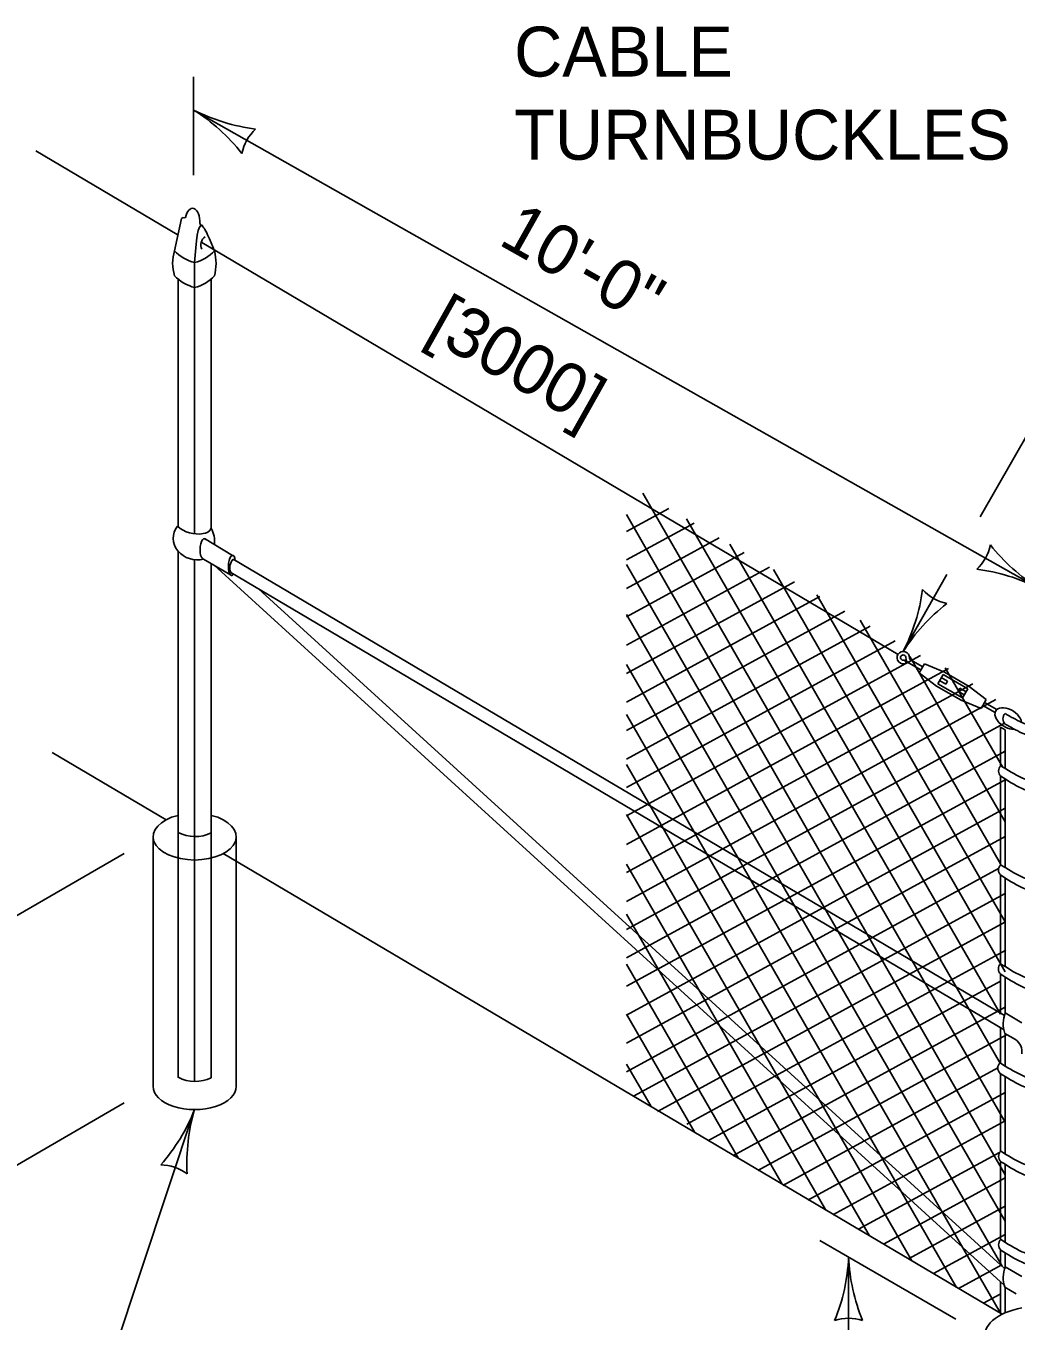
# Model space of a CAD drawing. Extents: x 49973.1 to 50021, y 49987.6 to 50015.4.
# Drawn here: x 50000.641 to 50001.832, y 49994.622 to 49996.179 of the extents above; entities that cross this region are included whole.
import ezdxf

# ---------------------------------------------------------------- set-up
doc = ezdxf.new("R2010")
doc.units = 0
for name, color, linetype in [('Level 1', 7, 'Continuous'), ('Level 2', 7, 'Continuous'), ('Level 3', 7, 'Continuous'), ('Level 4', 7, 'Continuous')]:
    doc.layers.add(name, color=color, linetype=linetype)

msp = doc.modelspace()

# ---------------------------------------------------------------- linework, layer by layer
at = {"layer": 'Level 1'}
for p, q in [((50000.823, 49995.9282), (50000.653, 49996.0287)), ((50000.8199, 49995.9087), (50000.8283, 49995.9476)), ((50000.8619, 49995.9231), (50000.868, 49995.9085)), ((50001.69, 49995.4236), (50000.8529, 49995.9185)), ((50000.8441, 49995.5685), (50000.8441, 49995.8944)), ((50000.8241, 49995.5771), (50000.8241, 49995.8748)), ((50000.8641, 49995.5748), (50000.8641, 49995.8748)), ((50001.8189, 49994.8612), (50001.3832, 49995.6173)), ((50001.3636, 49995.5713), (50001.4144, 49995.599)), ((50001.8189, 49994.7979), (50001.3636, 49995.5915)), ((50001.3636, 49995.5371), (50001.4447, 49995.5813)), ((50001.8133, 49994.9312), (50001.4357, 49995.5866)), ((50000.8898, 49995.5426), (50000.8558, 49995.5627)), ((50001.3636, 49995.5029), (50001.4749, 49995.5637)), ((50000.8241, 49995.2094), (50000.8241, 49995.5476)), ((50001.3636, 49995.4688), (50001.5051, 49995.546)), ((50001.8133, 49994.9911), (50001.4878, 49995.5561)), ((50000.8441, 49995.2044), (50000.8441, 49995.5373)), ((50000.8872, 49995.519), (50000.8548, 49995.5381)), ((50000.8641, 49995.209), (50000.8641, 49995.5326)), ((50000.8674, 49995.5307), (50001.8178, 49994.6655)), ((50001.8179, 49994.9895), (50000.8903, 49995.5378)), ((50001.8189, 49994.7421), (50001.3636, 49995.5315)), ((50001.8177, 49994.9722), (50000.8875, 49995.522)), ((50001.3636, 49995.4346), (50001.5354, 49995.5283)), ((50001.8189, 49995.042), (50001.5401, 49995.5256)), ((50000.9208, 49995.5023), (50001.8182, 49994.6855)), ((50001.3636, 49995.4006), (50001.5656, 49995.5107)), ((50001.3636, 49995.3662), (50001.5958, 49995.493)), ((50001.8189, 49995.1021), (50001.5924, 49995.495)), ((50001.3636, 49995.332), (50001.6261, 49995.4753)), ((50001.8154, 49994.688), (50001.3636, 49995.4713)), ((50001.3636, 49995.2975), (50001.6564, 49995.4576)), ((50001.8133, 49995.1718), (50001.6446, 49995.4645)), ((50001.3636, 49995.2635), (50001.6866, 49995.44)), ((50001.3636, 49995.2293), (50001.7169, 49995.4223)), ((50001.8131, 49994.6317), (50001.3636, 49995.4115)), ((50001.3636, 49995.1951), (50001.7507, 49995.4066)), ((50001.6979, 49995.4168), (50001.7, 49995.4131)), ((50001.7027, 49995.4134), (50001.7176, 49995.4049)), ((50001.8189, 49995.2222), (50001.7043, 49995.4209)), ((50001.7049, 49995.4171), (50001.7197, 49995.4086)), ((50001.7155, 49995.4012), (50001.7219, 49995.4123)), ((50001.7458, 49995.4022), (50001.7219, 49995.4123)), ((50001.8156, 49995.2883), (50001.7467, 49995.4074)), ((50001.7155, 49995.4012), (50001.7362, 49995.3855)), ((50001.7378, 49995.3883), (50001.7442, 49995.3995)), ((50001.7399, 49995.392), (50001.7473, 49995.3878)), ((50001.742, 49995.3957), (50001.7495, 49995.3915)), ((50001.7739, 49995.3823), (50001.7442, 49995.3995)), ((50001.7755, 49995.3851), (50001.7458, 49995.4022)), ((50001.7473, 49995.3878), (50001.7495, 49995.3915)), ((50001.3636, 49995.1612), (50001.78, 49995.3883)), ((50001.7659, 49995.3684), (50001.7362, 49995.3855)), ((50001.7675, 49995.3712), (50001.7378, 49995.3883)), ((50001.7622, 49995.3792), (50001.7643, 49995.3829)), ((50001.7696, 49995.3749), (50001.7622, 49995.3792)), ((50001.7718, 49995.3786), (50001.7643, 49995.3829)), ((50001.7675, 49995.3712), (50001.7739, 49995.3823)), ((50001.7962, 49995.3695), (50001.7755, 49995.3851)), ((50001.3636, 49995.1267), (50001.8076, 49995.3694)), ((50001.7659, 49995.3684), (50001.7898, 49995.3584)), ((50001.7898, 49995.3584), (50001.7962, 49995.3695)), ((50001.8067, 49995.3536), (50001.7919, 49995.3621)), ((50001.8088, 49995.3573), (50001.794, 49995.3658)), ((50001.7605, 49994.6627), (50001.3636, 49995.3513)), ((50001.3636, 49995.0928), (50001.818, 49995.3409)), ((50001.8133, 49995.2894), (50001.8133, 49995.3361)), ((50001.8133, 49995.3361), (50001.8189, 49995.3328)), ((50001.8189, 49995.286), (50001.8189, 49995.3328)), ((50000.8097, 49995.2248), (50000.6726, 49995.3058)), ((50001.3636, 49995.0589), (50001.8189, 49995.3071)), ((50001.7065, 49994.6947), (50001.3636, 49995.2911)), ((50001.3636, 49995.0247), (50001.8189, 49995.2729)), ((50001.8133, 49995.1703), (50001.8133, 49995.2775)), ((50001.8189, 49995.1668), (50001.8189, 49995.2735)), ((50001.3636, 49994.9899), (50001.8189, 49995.2388)), ((50001.6558, 49994.7246), (50001.3636, 49995.2312)), ((50000.7941, 49994.9044), (50000.7941, 49995.2044)), ((50000.8941, 49994.9044), (50000.8941, 49995.2044)), ((50001.3636, 49994.9562), (50001.8189, 49995.2047)), ((50001.8152, 49994.6304), (50000.8785, 49995.1841)), ((50001.6032, 49994.7557), (50001.3636, 49995.1712)), ((50001.3636, 49994.9219), (50001.811, 49995.166)), ((50001.8133, 49995.0514), (50001.8133, 49995.1584)), ((50001.8189, 49995.0479), (50001.8189, 49995.1542)), ((50001.372, 49994.8925), (50001.8189, 49995.1363)), ((50001.5508, 49994.7867), (50001.3636, 49995.1113)), ((50001.4009, 49994.874), (50001.8191, 49995.1022)), ((50001.4359, 49994.8589), (50001.8195, 49995.0682)), ((50001.4981, 49994.8178), (50001.3636, 49995.0512)), ((50001.8133, 49994.9921), (50001.8133, 49995.0394)), ((50001.8189, 49994.992), (50001.8189, 49995.0353)), ((50001.4614, 49994.8387), (50001.8133, 49995.0307)), ((50001.4456, 49994.8489), (50001.3636, 49994.9912)), ((50001.4914, 49994.8209), (50001.8182, 49994.9993)), ((50001.8189, 49994.9926), (50001.8391, 49994.9808)), ((50001.8133, 49994.9318), (50001.8133, 49994.975)), ((50001.5215, 49994.803), (50001.8203, 49994.9661)), ((50001.8186, 49994.968), (50001.8312, 49994.9606)), ((50001.8189, 49994.9282), (50001.8189, 49994.968)), ((50001.393, 49994.88), (50001.3636, 49994.931)), ((50001.5514, 49994.7853), (50001.8101, 49994.9264)), ((50001.8133, 49994.8262), (50001.8133, 49994.9195)), ((50001.8189, 49994.8226), (50001.8189, 49994.9159)), ((50001.5814, 49994.7675), (50001.8188, 49994.8971)), ((50001.6115, 49994.7497), (50001.8188, 49994.8628)), ((50001.6425, 49994.7325), (50001.8122, 49994.825)), ((50001.8133, 49994.7197), (50001.8133, 49994.8142)), ((50001.8189, 49994.7165), (50001.8189, 49994.8102)), ((50001.6726, 49994.7147), (50001.8187, 49994.7945)), ((50001.7027, 49994.6969), (50001.8189, 49994.7603)), ((50001.7328, 49994.6792), (50001.8189, 49994.7262)), ((50001.8133, 49994.69), (50001.8133, 49994.708)), ((50001.8189, 49994.6874), (50001.8189, 49994.7037)), ((50001.7629, 49994.6613), (50001.814, 49994.6893)), ((50001.8189, 49994.6874), (50001.8391, 49994.6756)), ((50001.8133, 49994.6316), (50001.8133, 49994.6696)), ((50001.8186, 49994.6628), (50001.832, 49994.6549)), ((50001.8189, 49994.6322), (50001.8189, 49994.6626)), ((50001.7929, 49994.6436), (50001.813, 49994.6545))]:
    msp.add_line(p, q, dxfattribs=at)
for centre, radius, start, end in [((50000.8213, 49995.962), 0.016, 295.9249, 302.4986), ((50000.8314, 49995.9511), 0.00296, 239.9045, 302.5213), ((50000.8494, 49995.9311), 0.00892, 58.7951, 78.2043), ((50000.8636, 49995.9157), 0.0121, 124.9931, 205.1052), ((50000.8672, 49995.8937), 0.0496, 162.4104, 197.5823), ((50000.8575, 49995.9448), 0.0521, 223.7766, 255.0811), ((50000.832, 49995.9422), 0.0492, 284.1707, 316.9106), ((50000.8065, 49995.8935), 0.0633, 346.2869, 13.7075), ((50000.8575, 49995.9148), 0.0521, 223.7766, 255.0811), ((50000.832, 49995.9122), 0.0492, 284.1707, 316.9078), ((50000.8421, 49995.563), 0.0237, 141.8752, 219.6636), ((50000.8484, 49995.6059), 0.0377, 228.7121, 279.0641), ((50000.8544, 49995.5789), 0.0102, 269.16, 338.2202), ((50000.8364, 49995.5594), 0.0317, 352.9842, 29.8194), ((50000.8473, 49995.5681), 0.0309, 220.7866, 284.0306), ((50000.9012, 49995.5277), 0.0149, 137.2659, 202.5526), ((50000.8797, 49995.5374), 0.0127, 356.242, 19.29), ((50000.8842, 49995.5219), 0.00599, 320.3441, 346.2477), ((50001.6963, 49995.4196), 0.00749, 356.4626, 299.1398), ((50001.6963, 49995.4196), 0.00321, 356.4626, 299.809), ((50001.706, 49995.419), 0.00642, 176.4626, 240.0748), ((50001.706, 49995.419), 0.00214, 176.4626, 240.0748), ((50001.8249, 49995.3462), 0.00871, 133.7268, 227.704), ((50001.8196, 49995.2834), 0.00871, 133.6634, 227.09), ((50000.8445, 49995.249), 0.0445, 242.7309, 296.121), ((50001.8195, 49995.1644), 0.00871, 133.6634, 227.09), ((50001.8194, 49995.0454), 0.00871, 133.6634, 227.09), ((50001.8511, 49994.9799), 0.0346, 158.48, 200.0855), ((50001.821, 49994.9457), 0.0181, 352.1171, 54.7359), ((50001.8187, 49994.9263), 0.00871, 133.6634, 227.09), ((50001.8196, 49994.8202), 0.00871, 133.6634, 227.09), ((50001.8196, 49994.7139), 0.00871, 133.6634, 227.09), ((50001.8511, 49994.6747), 0.0346, 158.48, 200.0855)]:
    msp.add_arc(centre, radius, start, end, dxfattribs=at)
for centre, major_axis, ratio, start_param, end_param in [((50000.8414, 49995.9422), (0.0001, 0.0176), 0.514964, 4.687034, 7.484081), ((50000.8553, 49995.5504), (0.0005, 0.0123), 0.386165, 5.88302, 9.422279), ((50000.8894, 49995.5303), (0.0005, 0.0123), 0.386165, 5.88302, 9.404785), ((50001.8225, 49995.3465), (-0.015, 0.009), 0.610393, 3.559041, 7.997344), ((50001.8225, 49995.3465), (-0.015, 0.009), 0.610393, 1.714159, 2.374886), ((50000.8441, 49995.2044), (-0.05, 0), 0.560136, 5.123906, 10.584057), ((50000.8441, 49994.9044), (-0.05, 0), 0.560136, 0, 3.141593), ((50001.8591, 49994.6044), (0.065, 0), 0.543263, 1.883563, 7.541224)]:
    msp.add_ellipse(centre, major_axis=major_axis, ratio=ratio, start_param=start_param, end_param=end_param, dxfattribs=at)
for points in [[(50000.8441, 49995.8944), (50000.8536, 49995.9382), (50000.8619, 49995.9231)], [(50000.8505, 49995.9417), (50000.8507, 49995.9404), (50000.8512, 49995.9398)], [(50001.8188, 49995.3525), (50001.8391, 49995.3417), (50001.8591, 49995.3364), (50001.8797, 49995.3417)], [(50001.819, 49995.3398), (50001.8392, 49995.329), (50001.8592, 49995.3237), (50001.8798, 49995.329)], [(50001.8136, 49995.2897), (50001.8391, 49995.2751), (50001.8591, 49995.2698), (50001.8797, 49995.2751)], [(50001.8137, 49995.277), (50001.8392, 49995.2624), (50001.8592, 49995.2571), (50001.8798, 49995.2624)], [(50001.8135, 49995.1707), (50001.839, 49995.1561), (50001.859, 49995.1508), (50001.8796, 49995.1561)], [(50001.8136, 49995.158), (50001.8391, 49995.1434), (50001.8591, 49995.1381), (50001.8797, 49995.1434)], [(50001.8134, 49995.0517), (50001.8389, 49995.0371), (50001.8589, 49995.0318), (50001.8795, 49995.0371)], [(50001.8135, 49995.039), (50001.839, 49995.0244), (50001.859, 49995.0191), (50001.8796, 49995.0244)], [(50001.8127, 49994.9326), (50001.8382, 49994.918), (50001.8582, 49994.9127), (50001.8788, 49994.918)], [(50001.8128, 49994.9199), (50001.8383, 49994.9053), (50001.8583, 49994.9), (50001.8789, 49994.9053)], [(50001.8136, 49994.8265), (50001.8391, 49994.8119), (50001.8591, 49994.8066), (50001.8797, 49994.8119)], [(50001.8137, 49994.8138), (50001.8392, 49994.7992), (50001.8592, 49994.7939), (50001.8798, 49994.7992)], [(50001.8136, 49994.7202), (50001.8391, 49994.7056), (50001.8591, 49994.7003), (50001.8797, 49994.7056)], [(50001.8137, 49994.7075), (50001.8392, 49994.6929), (50001.8592, 49994.6876), (50001.8798, 49994.6929)]]:
    msp.add_spline(points, degree=3, dxfattribs=at)
at = {"layer": 'Level 3'}
for p, q in [((50000.8429, 49995.9996), (50000.8429, 49996.1177)), ((50000.8429, 49996.0777), (50001.7518, 49995.5638)), ((50001.7886, 49995.5889), (50002.0519, 49996.0481)), ((50001.7518, 49995.5638), (50001.8591, 49995.5031)), ((50001.6962, 49995.4271), (50001.7488, 49995.5195)), ((50000.7595, 49995.1844), (50000.5723, 49995.0763)), ((50000.7595, 49994.8844), (50000.5723, 49994.7763)), ((50000.8439, 49994.8764), (50000.7315, 49994.5389)), ((50001.7595, 49994.6245), (50001.5959, 49994.719)), ((50001.6305, 49994.3789), (50001.6305, 49994.699))]:
    msp.add_line(p, q, dxfattribs=at)
for centre, radius, start, end in [((50000.7256, 49995.8889), 0.2223, 37.9705, 58.154), ((50000.9474, 49996.286), 0.233, 243.3418, 262.5916), ((50000.9545, 49996.0146), 0.0548, 132.6533, 168.3756), ((50001.7475, 49995.5662), 0.0548, 312.6533, 348.3756), ((50001.9764, 49995.692), 0.2223, 217.9705, 238.154), ((50001.7546, 49995.2949), 0.233, 63.3418, 82.5916), ((50001.4989, 49995.5296), 0.2223, 332.5308, 352.7143), ((50001.76, 49995.5383), 0.0548, 222.3092, 258.0315), ((50001.8923, 49995.3013), 0.233, 128.0932, 147.343), ((50000.6368, 49994.9572), 0.2223, 318.4999, 338.6834), ((50001.0677, 49994.8117), 0.233, 163.8712, 183.1211), ((50000.8022, 49994.7552), 0.0548, 53.1827, 88.9051), ((50001.4084, 49994.7081), 0.2223, 337.456, 357.6395), ((50001.8632, 49994.7105), 0.233, 182.8273, 202.0772), ((50001.6305, 49994.5708), 0.0548, 72.1388, 107.8612)]:
    msp.add_arc(centre, radius, start, end, dxfattribs=at)
at = {"layer": 'Level 4'}
for p, q in [((50000.8241, 49995.2094), (50000.8241, 49994.9151)), ((50000.8441, 49995.2044), (50000.8441, 49994.91)), ((50000.8641, 49995.209), (50000.8641, 49994.9146))]:
    msp.add_line(p, q, dxfattribs=at)
msp.add_arc((50000.8446, 49994.9547), 0.0445, 242.586, 295.9785, dxfattribs=at)

# ---------------------------------------------------------------- texts
at = {"layer": 'Level 2'}
for s, p in [('CABLE', (50001.2283, 49996.1181)), ('TURNBUCKLES', (50001.2283, 49996.0181))]:
    msp.add_text(s, height=0.06, dxfattribs=at).set_placement(p)
for s, p in [('10\'-0"', (50001.2078, 49995.9171)), ('[3000]', (50001.1202, 49995.8057))]:
    msp.add_text(s, height=0.06, rotation=330.6353, dxfattribs=at).set_placement(p)

doc.saveas('drawing.dxf')
